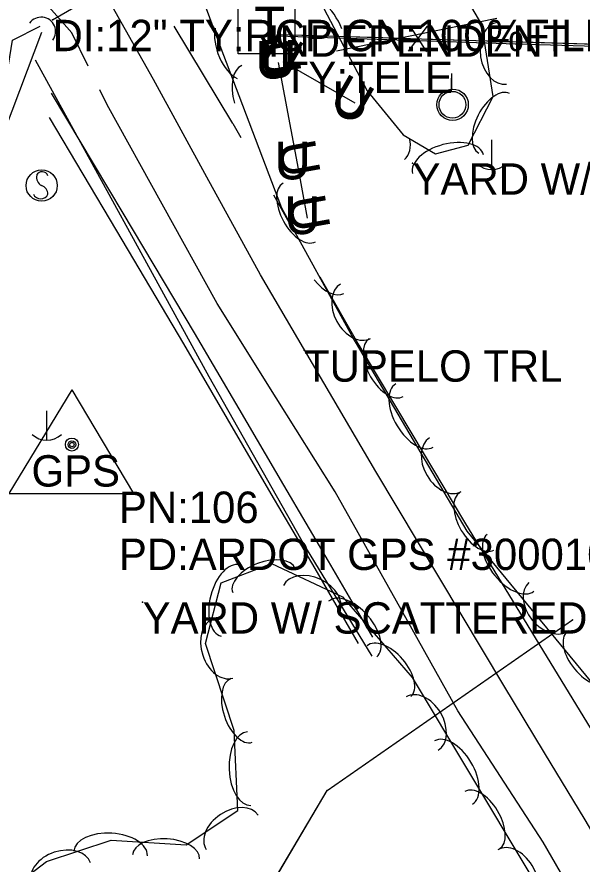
# Model space of a CAD drawing. Extents: x 954793 to 988390, y 1867850 to 1924428.
# Drawn here: x 961374.7 to 961464.8, y 1906753 to 1906888 of the extents above; entities that cross this region are included whole.
import ezdxf

# ---------------------------------------------------------------- set-up
doc = ezdxf.new("R2010")
doc.units = 0
for name, color, linetype in [('Default', 7, 'Continuous'), ('S_CROSS_DRAIN', 7, 'Continuous'), ('S_DITCHLINE', 7, 'Continuous'), ('S_DRG_PT_SYM', 7, 'Continuous'), ('S_EDGE_PAVEMENT', 7, 'Continuous'), ('S_FENCE', 7, 'Continuous'), ('S_MSC_PT_SYM', 7, 'Continuous'), ('S_PAVEMENT_CROWN', 7, 'Continuous'), ('S_PRIMARY_CTL', 7, 'Continuous'), ('S_PRIMARY_CTL_ANNOT', 7, 'Continuous'), ('S_SIDE_DRAIN', 7, 'Continuous'), ('S_SIDE_DRAIN_ANNOT', 7, 'Continuous'), ('S_SIGN', 7, 'Continuous'), ('S_STREAM', 7, 'Continuous'), ('S_SURVEY_TEXT_ANNOT', 7, 'Continuous'), ('S_TELEPHONE_UTILITIES', 7, 'Continuous'), ('S_TELEPHONE_UTILITIES_ANNOT', 7, 'Continuous'), ('S_TREE', 7, 'Continuous'), ('S_UNDERGROUND_CABLE', 7, 'Continuous'), ('S_UNDERGROUND_CABLE_ANNOT', 7, 'Continuous'), ('S_UTILITY_POLE', 7, 'Continuous'), ('S_UTL_PT_SYM', 7, 'Continuous'), ('S_WATER_UTILITIES', 7, 'Continuous')]:
    doc.layers.add(name, color=color, linetype=linetype)

msp = doc.modelspace()

# ---------------------------------------------------------------- linework, layer by layer
at = {"layer": 'S_CROSS_DRAIN'}
msp.add_arc((961378.54, 1906885.7), 2.3, 323.3967, 143.7259, dxfattribs=at)
at = {"layer": 'S_DITCHLINE'}
for points in [[(961281.36, 1906504.67), (961286.92, 1906523.21), (961292.47, 1906541.76), (961298.03, 1906560.31), (961303.59, 1906578.85), (961308.97, 1906596.26), (961314.35, 1906613.67), (961319.73, 1906631.07), (961325.12, 1906648.48), (961330.22, 1906665.83), (961335.33, 1906683.19), (961340.43, 1906700.54), (961345.54, 1906717.9), (961348.74, 1906734.13), (961351.94, 1906750.37), (961355.14, 1906766.6), (961358.34, 1906782.84), (961361.82, 1906806.99), (961365.31, 1906831.14), (961367.48, 1906844.45), (961369.65, 1906857.75), (961371.81, 1906871.05), (961373.98, 1906884.36), (961378.38, 1906886.56)], [(961380.13, 1906875.89), (961391.55, 1906856.78), (961402.96, 1906837.67), (961410.07, 1906825.54), (961417.18, 1906813.41), (961424.3, 1906801.27), (961431.41, 1906789.14)], [(961379.82, 1906872), (961390.54, 1906853.95), (961401.27, 1906835.9), (961408.23, 1906823.97), (961415.2, 1906812.03), (961422.17, 1906800.1), (961429.13, 1906788.16)]]:
    msp.add_lwpolyline(points, dxfattribs=at)
at = {"layer": 'S_DRG_PT_SYM'}
msp.add_lwpolyline([(961380.36, 1906887.58), (961380.33, 1906887.63), (961380.36, 1906887.58), (961380.31, 1906887.56), (961380.36, 1906887.58), (961380.38, 1906887.54), (961380.36, 1906887.58), (961380.4, 1906887.61)], close=True, dxfattribs=at)
msp.add_lwpolyline([(961380.36, 1906887.58), (961380.33, 1906887.63), (961380.36, 1906887.58), (961380.31, 1906887.56), (961380.36, 1906887.58), (961380.38, 1906887.54), (961380.36, 1906887.58), (961380.4, 1906887.61)], close=True, dxfattribs=at)
msp.add_lwpolyline([(961380.36, 1906887.58), (961380.36, 1906887.63), (961380.36, 1906887.58), (961380.31, 1906887.58), (961380.36, 1906887.58), (961380.36, 1906887.53), (961380.36, 1906887.58), (961380.41, 1906887.58)], dxfattribs=at)
at = {"layer": 'S_EDGE_PAVEMENT'}
for points in [[(961386.04, 1906880.2), (961383.44, 1906885.51), (961379.8, 1906889.6), (961376.08, 1906891.47), (961375.51, 1906891.45)], [(961409.13, 1906871.03), (961399.77, 1906886.58)], [(961492.81, 1906693.27), (961484.69, 1906708.9), (961478.28, 1906721.04), (961468.32, 1906739.74), (961458.61, 1906756.49), (961445.02, 1906777.42), (961435.22, 1906794.88), (961425.43, 1906812.34), (961416.02, 1906827.34), (961406.61, 1906842.34), (961397.83, 1906858.19), (961389.05, 1906874.04), (961387.89, 1906876.41)], [(961409.13, 1906871.03), (961410.37, 1906868.84)], [(961415.58, 1906859.68), (961418.87, 1906853.91)], [(961423.02, 1906846.61), (961429.23, 1906835.69), (961437.66, 1906821.58), (961446.09, 1906807.47), (961456.78, 1906789.99), (961467.46, 1906772.51), (961477.28, 1906755.08), (961487.1, 1906737.66), (961497.45, 1906719.69), (961507.81, 1906701.72), (961517.59, 1906682.99), (961526.79, 1906665.51)]]:
    msp.add_lwpolyline(points, dxfattribs=at)
at = {"layer": 'S_FENCE'}
for p, q in [((961437.16, 1906882.57), (961440.15, 1906886.58)), ((961437.28, 1906886.66), (961440.02, 1906882.48))]:
    msp.add_line(p, q, dxfattribs=at)
for points in [[(961416.66, 1906885.25), (961436.65, 1906884.63)], [(961416.66, 1906885.25), (961546.74, 1906881.25)], [(961505.26, 1906882.19), (961454.29, 1906883.68), (961416.3, 1906884.95)], [(961505.26, 1906882.19), (961454.29, 1906883.68), (961416.3, 1906884.95)], [(961440.65, 1906884.51), (961460.65, 1906883.9)], [(961460.65, 1906883.9), (961480.64, 1906883.28)]]:
    msp.add_lwpolyline(points, dxfattribs=at)
at = {"layer": 'S_MSC_PT_SYM'}
for points in [[(961416.3, 1906884.95), (961416.3, 1906884.9), (961416.3, 1906884.95), (961416.35, 1906884.95), (961416.3, 1906884.95), (961416.3, 1906885), (961416.3, 1906884.95), (961416.25, 1906884.95)], [(961416.3, 1906884.95), (961416.3, 1906884.9), (961416.3, 1906884.95), (961416.35, 1906884.95), (961416.3, 1906884.95), (961416.3, 1906885), (961416.3, 1906884.95), (961416.25, 1906884.95)], [(961454.29, 1906883.68), (961454.29, 1906883.63), (961454.29, 1906883.68), (961454.34, 1906883.67), (961454.29, 1906883.68), (961454.29, 1906883.73), (961454.29, 1906883.68), (961454.24, 1906883.68)], [(961454.29, 1906883.68), (961454.29, 1906883.63), (961454.29, 1906883.68), (961454.34, 1906883.67), (961454.29, 1906883.68), (961454.29, 1906883.73), (961454.29, 1906883.68), (961454.24, 1906883.68)], [(961437.78, 1906864.7), (961437.78, 1906864.75), (961437.78, 1906864.7), (961437.73, 1906864.7), (961437.78, 1906864.7), (961437.78, 1906864.65), (961437.78, 1906864.7), (961437.83, 1906864.7)], [(961437.78, 1906864.7), (961437.78, 1906864.75), (961437.78, 1906864.7), (961437.73, 1906864.7), (961437.78, 1906864.7), (961437.78, 1906864.65), (961437.78, 1906864.7), (961437.83, 1906864.7)], [(961420.47, 1906834.89), (961420.47, 1906834.94), (961420.47, 1906834.89), (961420.42, 1906834.89), (961420.47, 1906834.89), (961420.47, 1906834.84), (961420.47, 1906834.89), (961420.52, 1906834.89)], [(961420.47, 1906834.89), (961420.47, 1906834.94), (961420.47, 1906834.89), (961420.42, 1906834.89), (961420.47, 1906834.89), (961420.47, 1906834.84), (961420.47, 1906834.89), (961420.52, 1906834.89)], [(961394.73, 1906794.73), (961394.73, 1906794.78), (961394.73, 1906794.73), (961394.68, 1906794.73), (961394.73, 1906794.73), (961394.73, 1906794.68), (961394.73, 1906794.73), (961394.78, 1906794.73)], [(961394.73, 1906794.73), (961394.73, 1906794.78), (961394.73, 1906794.73), (961394.68, 1906794.73), (961394.73, 1906794.73), (961394.73, 1906794.68), (961394.73, 1906794.73), (961394.78, 1906794.73)]]:
    msp.add_lwpolyline(points, close=True, dxfattribs=at)
for points in [[(961416.3, 1906884.95), (961416.3, 1906885), (961416.3, 1906884.95), (961416.25, 1906884.95), (961416.3, 1906884.95), (961416.3, 1906884.9), (961416.3, 1906884.95), (961416.35, 1906884.95)], [(961454.29, 1906883.68), (961454.29, 1906883.73), (961454.29, 1906883.68), (961454.24, 1906883.68), (961454.29, 1906883.68), (961454.29, 1906883.63), (961454.29, 1906883.68), (961454.34, 1906883.68)], [(961437.78, 1906864.7), (961437.78, 1906864.75), (961437.78, 1906864.7), (961437.73, 1906864.7), (961437.78, 1906864.7), (961437.78, 1906864.65), (961437.78, 1906864.7), (961437.83, 1906864.7)], [(961420.47, 1906834.89), (961420.47, 1906834.94), (961420.47, 1906834.89), (961420.42, 1906834.89), (961420.47, 1906834.89), (961420.47, 1906834.84), (961420.47, 1906834.89), (961420.52, 1906834.89)], [(961394.73, 1906794.73), (961394.73, 1906794.78), (961394.73, 1906794.73), (961394.68, 1906794.73), (961394.73, 1906794.73), (961394.73, 1906794.68), (961394.73, 1906794.73), (961394.78, 1906794.73)]]:
    msp.add_lwpolyline(points, dxfattribs=at)
at = {"layer": 'S_PAVEMENT_CROWN'}
msp.add_lwpolyline([(961523.15, 1906664.32), (961513.68, 1906679.63), (961504.2, 1906694.93), (961501.49, 1906698.88), (961493.04, 1906713.12), (961484.59, 1906727.36), (961474.95, 1906743.69), (961465.32, 1906760.02), (961458.83, 1906770.73), (961452.35, 1906781.44), (961442.15, 1906798.5), (961431.95, 1906815.56), (961422.74, 1906831.23), (961413.53, 1906846.9), (961404.99, 1906862.48), (961396.46, 1906878.06), (961388.72, 1906891.89), (961381.89, 1906903.84), (961375.06, 1906915.79)], dxfattribs=at)
at = {"layer": 'S_PRIMARY_CTL'}
for p, q in [((961383.44, 1906828.57), (961373.41, 1906812.06)), ((961383.44, 1906828.57), (961393.26, 1906812.06)), ((961373.41, 1906812.06), (961393.26, 1906812.06))]:
    msp.add_line(p, q, dxfattribs=at)
for radius in [1.04, 0.609, 0.344]:
    msp.add_circle((961383.44, 1906819.87), radius, dxfattribs=at)
at = {"layer": 'S_SIDE_DRAIN'}
msp.add_line((961380.36, 1906887.58), (961398.51, 1906898.1), dxfattribs=at)
msp.add_lwpolyline([(961380.36, 1906887.58), (961398.51, 1906898.1)], dxfattribs=at)
msp.add_lwpolyline([(961380.36, 1906887.58), (961398.51, 1906898.1)], dxfattribs=at)
at = {"layer": 'S_SIGN'}
msp.add_circle((961378.63, 1906861.15), 2.49, dxfattribs=at)
for centre, radius, start, end in [((961379.31, 1906862.48), 1.5, 167.1196, 241.9813), ((961378.7, 1906862.42), 0.95, 16.5258, 156.8957), ((961378.22, 1906859.81), 1.4, 358.6529, 73.7063), ((961378.47, 1906860.33), 1.28, 204.641, 335.359)]:
    msp.add_arc(centre, radius, start, end, dxfattribs=at)
at = {"layer": 'S_STREAM'}
for points in [[(961335.05, 1906677.93), (961337.91, 1906688.07), (961349.66, 1906732.23), (961365.1, 1906802.39), (961368.14, 1906818.27), (961368.84, 1906838.53), (961370.35, 1906863.76), (961378.65, 1906885.63)], [(961377.6, 1906881.22), (961405.28, 1906830.71), (961420.79, 1906803.27), (961431.28, 1906786.15)]]:
    msp.add_lwpolyline(points, dxfattribs=at)
at = {"layer": 'S_TELEPHONE_UTILITIES'}
msp.add_lwpolyline([(961409.98, 1906882.17), (961409.98, 1906891.17), (961418.98, 1906891.17), (961418.98, 1906882.17)], close=True, dxfattribs=at)
at = {"layer": 'S_TREE'}
for points in [[(961387.56, 1906978.78), (961401.71, 1906940.3), (961409.55, 1906919.57), (961415.82, 1906903.33), (961423.63, 1906889.38), (961430.53, 1906876.24), (961436.31, 1906869.25), (961441.46, 1906866.23), (961446.63, 1906867.59), (961450.65, 1906875.38), (961448.86, 1906886.83), (961443.33, 1906896.28), (961446.7, 1906904.48), (961461.61, 1906909.13), (961487.61, 1906907.29), (961516.15, 1906906.41), (961540.77, 1906905.75), (961551.34, 1906905.98)], [(961543.62, 1906812.71), (961536.81, 1906825.45), (961533.14, 1906841.29), (961532.11, 1906858.11), (961525.32, 1906871.05), (961515.01, 1906875.55), (961505.27, 1906874.07), (961494.28, 1906868.9), (961483.76, 1906859.14), (961476.22, 1906846.1), (961475.72, 1906827.56), (961478.11, 1906814.97), (961483, 1906794.4), (961486.49, 1906781.07), (961485.07, 1906775.68), (961477.71, 1906773.28), (961466.18, 1906782.2), (961446.52, 1906806.05), (961428.16, 1906837.15), (961416.91, 1906857.56), (961407.11, 1906883.41), (961397.78, 1906908.65)], [(961451.23, 1906887.8), (961425.63, 1906882.59)], [(961373.78, 1906749.07), (961379.38, 1906753.38), (961389.72, 1906756.8), (961401.69, 1906756.06), (961409.92, 1906761.51), (961409.35, 1906774.26), (961404.76, 1906788.14), (961407.27, 1906797.84), (961415.29, 1906800.92), (961426.62, 1906795.57), (961437.71, 1906782.71), (961484.11, 1906705.42), (961524.32, 1906640.21)]]:
    msp.add_lwpolyline(points, dxfattribs=at)
for centre, major_axis, ratio, start_param, end_param in [((961423.12, 1906885.79), (-2.73, 5.2), 0.55008, 4.49994, 6.283185), ((961451.99, 1906882.23), (0.77, -4.9), 0.685311, 3.141593, 6.283185), ((961409.5, 1906883.07), (1.9, -5), 0.540699, 3.839951, 5.76842), ((961412.65, 1906874.78), (2.08, -5.49), 0.55008, 3.141593, 4.591533), ((961450.82, 1906871.08), (-2.45, -4.75), 0.540699, 3.141593, 6.283185), ((961433.33, 1906869.11), (-3.16, 3.82), 0.685311, 3.141593, 4.109621), ((961443.45, 1906864.56), (-5.67, -1.49), 0.55008, 3.141593, 6.283185), ((961419.71, 1906856.87), (2.58, -4.68), 0.540699, 3.141593, 6.283185), ((961423.99, 1906849.11), (2.83, -5.14), 0.55008, 5.009864, 6.283185), ((961428.69, 1906841.12), (2.39, -4.34), 0.685311, 3.141593, 6.283185), ((961433.58, 1906832.13), (2.72, -4.6), 0.540699, 3.141593, 6.283185), ((961438.09, 1906824.5), (2.98, -5.05), 0.55008, 3.141593, 6.283185), ((961443.02, 1906816.66), (2.52, -4.27), 0.685311, 3.141593, 6.283185), ((961448.04, 1906807.65), (2.72, -4.6), 0.540699, 3.141593, 6.283185), ((961453.41, 1906801.02), (3.73, -4.53), 0.55008, 3.141593, 6.283185), ((961414.08, 1906798.19), (-4.99, -1.92), 0.540699, 3.141593, 6.283185), ((961408.72, 1906795), (-1.47, -5.68), 0.55008, 3.141593, 6.283185), ((961421.68, 1906795.27), (-4.48, 2.12), 0.685311, 3.141593, 6.283185), ((961459.5, 1906794.05), (3.15, -3.82), 0.685311, 3.141593, 6.283185), ((961428.23, 1906790.45), (-3.83, 4.44), 0.55008, 3.141593, 6.283185), ((961407.53, 1906787.35), (1.56, -4.7), 0.685311, 3.141593, 6.283185), ((961465.85, 1906785.93), (3.4, -4.13), 0.540699, 3.141593, 6.283185), ((961434.02, 1906783.74), (-3.49, 4.05), 0.540699, 3.141593, 6.283185), ((961410.52, 1906777.48), (1.68, -5.08), 0.540699, 3.141593, 6.283185), ((961439.33, 1906775.39), (-2.55, 4.25), 0.685311, 3.141593, 6.283185), ((961411.74, 1906768.19), (0.26, -5.86), 0.55008, 3.141593, 6.283185), ((961444.32, 1906767.58), (-3.02, 5.03), 0.55008, 3.141593, 6.283185), ((961448.88, 1906759.98), (-2.75, 4.58), 0.540699, 3.141593, 6.283185), ((961409.01, 1906758.05), (-4.13, -2.74), 0.685311, 3.141593, 6.283185), ((961389.62, 1906754.68), (-5.86, 0.36), 0.55008, 3.141593, 6.283185), ((961398.47, 1906754.13), (-5.34, 0.33), 0.540699, 3.141593, 6.283185), ((961381.7, 1906751.64), (-4.71, -1.55), 0.685311, 3.141593, 6.283185), ((961453.96, 1906751.01), (-2.55, 4.25), 0.685311, 3.141593, 6.283185)]:
    msp.add_ellipse(centre, major_axis=major_axis, ratio=ratio, start_param=start_param, end_param=end_param, dxfattribs=at)
at = {"layer": 'S_UNDERGROUND_CABLE'}
for p, q in [((961416.33, 1906880.75), (961419.38, 1906864.68)), ((961417.09, 1906880.91), (961428.58, 1906874.33)), ((961419.38, 1906864.68), (961420.95, 1906855.97))]:
    msp.add_line(p, q, dxfattribs=at)
for points in [[(961416.33, 1906880.75), (961419.38, 1906864.68), (961420.95, 1906855.97)], [(961416.33, 1906880.75), (961419.38, 1906864.68), (961420.95, 1906855.97)], [(961417.09, 1906880.91), (961428.58, 1906874.33)], [(961417.09, 1906880.91), (961428.58, 1906874.33)]]:
    msp.add_lwpolyline(points, dxfattribs=at)
at = {"layer": 'S_UTILITY_POLE'}
for p, q in [((961444.03, 1906876.56), (961444.03, 1906879.04)), ((961444.02, 1906876.18), (961444.02, 1906878.28)), ((961450.36, 1906868.42), (961450.36, 1906863.69)), ((961379.37, 1906825.26), (961379.37, 1906820.53))]:
    msp.add_line(p, q, dxfattribs=at)
for centre, radius in [((961444.18, 1906874.04), 2.5), ((961444.14, 1906874.04), 2.13)]:
    msp.add_circle(centre, radius, dxfattribs=at)
for centre in [(961450.42, 1906867.11), (961379.44, 1906823.96)]:
    msp.add_arc(centre, 3.41, 226.3972, 313.6028, dxfattribs=at)
at = {"layer": 'S_UTL_PT_SYM'}
for points in [[(961463.28, 1906791.93), (961463.28, 1906791.98), (961463.28, 1906791.93), (961463.23, 1906791.93), (961463.28, 1906791.93), (961463.28, 1906791.88), (961463.28, 1906791.93), (961463.33, 1906791.93)], [(961424.18, 1906764.72), (961424.18, 1906764.77), (961424.18, 1906764.72), (961424.13, 1906764.72), (961424.18, 1906764.72), (961424.18, 1906764.67), (961424.18, 1906764.72), (961424.23, 1906764.72)]]:
    msp.add_lwpolyline(points, dxfattribs=at)
for points in [[(961463.28, 1906791.93), (961463.25, 1906791.97), (961463.28, 1906791.93), (961463.24, 1906791.9), (961463.28, 1906791.93), (961463.3, 1906791.89), (961463.28, 1906791.93), (961463.32, 1906791.96)], [(961463.28, 1906791.93), (961463.25, 1906791.97), (961463.28, 1906791.93), (961463.24, 1906791.9), (961463.28, 1906791.93), (961463.3, 1906791.89), (961463.28, 1906791.93), (961463.32, 1906791.96)], [(961424.18, 1906764.72), (961424.15, 1906764.76), (961424.18, 1906764.72), (961424.14, 1906764.69), (961424.18, 1906764.72), (961424.21, 1906764.68), (961424.18, 1906764.72), (961424.22, 1906764.75)], [(961424.18, 1906764.72), (961424.15, 1906764.76), (961424.18, 1906764.72), (961424.14, 1906764.69), (961424.18, 1906764.72), (961424.21, 1906764.68), (961424.18, 1906764.72), (961424.22, 1906764.75)]]:
    msp.add_lwpolyline(points, close=True, dxfattribs=at)
at = {"layer": 'S_WATER_UTILITIES'}
for p, q in [((961424.18, 1906764.72), (961463.28, 1906791.93)), ((961403.29, 1906729.43), (961424.18, 1906764.72))]:
    msp.add_line(p, q, dxfattribs=at)
msp.add_lwpolyline([(961294.67, 1906268.34), (961326.07, 1906306.57), (961356.32, 1906361.61), (961375.39, 1906423.95), (961379.64, 1906542.05), (961383.73, 1906581.01), (961389.19, 1906618.08), (961390.5, 1906624.95), (961371, 1906630.25), (961374.35, 1906647.04), (961391.98, 1906702.43), (961403.29, 1906729.43), (961424.18, 1906764.72), (961463.28, 1906791.93)], dxfattribs=at)
msp.add_lwpolyline([(961294.67, 1906268.34), (961326.07, 1906306.57), (961356.32, 1906361.61), (961375.39, 1906423.95), (961379.64, 1906542.05), (961383.73, 1906581.01), (961389.19, 1906618.08), (961390.5, 1906624.95), (961371, 1906630.25), (961374.35, 1906647.04), (961391.98, 1906702.43), (961403.29, 1906729.43), (961424.18, 1906764.72), (961463.28, 1906791.93)], dxfattribs=at)

# ---------------------------------------------------------------- texts
at = {"layer": 'Default'}
for rotation, p in [(330.2182, (961412.67, 1906880.5)), (360, (961412.7, 1906878.21)), (280.7591, (961413.15, 1906883.84)), (360, (961413.46, 1906878.36)), (330.2182, (961424.17, 1906873.92)), (360, (961424.95, 1906871.78)), (360, (961415.75, 1906862.14)), (280.2081, (961416.23, 1906867.8)), (360, (961417.32, 1906853.42)), (280.2081, (961417.8, 1906859.09))]:
    msp.add_text('U', height=6, rotation=rotation, dxfattribs=at).set_placement(p)
at = {"layer": 'S_PRIMARY_CTL'}
msp.add_text('GPS', height=5, rotation=360, dxfattribs=at).set_placement((961377, 1906813.17))
at = {"layer": 'S_PRIMARY_CTL_ANNOT'}
for s, p in [('PN:106', (961390.94, 1906807.37)), ('PD:ARDOT GPS #300010A', (961390.94, 1906799.87))]:
    msp.add_text(s, height=5, dxfattribs=at).set_placement(p)
at = {"layer": 'S_SIDE_DRAIN_ANNOT'}
msp.add_text('DI:12" TY:RCP CN:100%FILL BTTM ', height=5, dxfattribs=at).set_placement((961380.36, 1906882.58))
at = {"layer": 'S_SURVEY_TEXT_ANNOT'}
for s, p in [('YARD W/ SCATTERED TREES', (961437.78, 1906859.7)), ('TUPELO TRL', (961420.47, 1906829.89)), ('YARD W/ SCATTERED TREES', (961394.73, 1906789.73))]:
    msp.add_text(s, height=5, dxfattribs=at).set_placement(p)
at = {"layer": 'S_TELEPHONE_UTILITIES'}
msp.add_text('T', height=6, rotation=360, dxfattribs=at).set_placement((961412.54, 1906883.67))
at = {"layer": 'S_TELEPHONE_UTILITIES_ANNOT'}
msp.add_text('INDEPENDENT', height=5, dxfattribs=at).set_placement((961414.71, 1906881.69))
at = {"layer": 'S_UNDERGROUND_CABLE_ANNOT'}
msp.add_text('TY:TELE', height=5, dxfattribs=at).set_placement((961417.09, 1906875.91))

doc.saveas('drawing.dxf')
